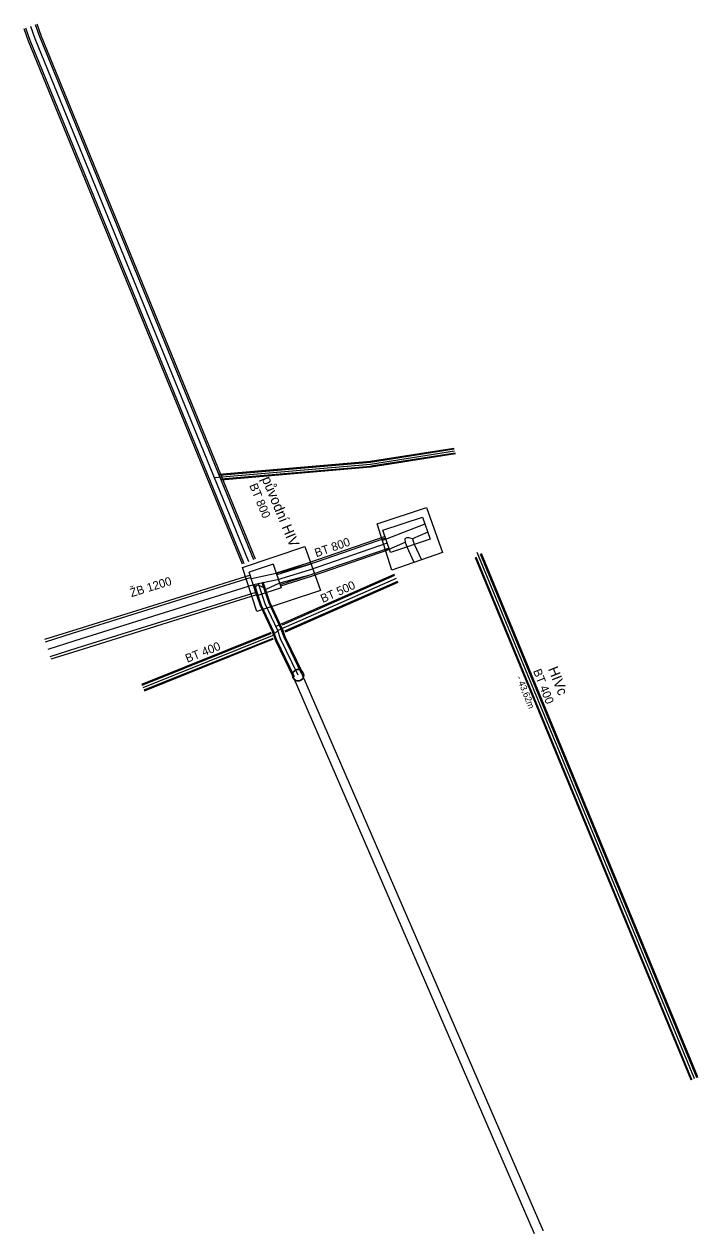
# Model space of a CAD drawing. Extents: x -969087 to -122837, y -1605141 to -636627.
# Drawn here: x -545312.4 to -545245.3, y -1121581.6 to -1121461.1 of the extents above; entities that cross this region are included whole.
import ezdxf

# ---------------------------------------------------------------- set-up
doc = ezdxf.new("R2010")
doc.units = 0
for name, color, linetype in [('Vrstva 14', 7, 'Continuous'), ('Vrstva 2', 7, 'Continuous'), ('Vrstva 5', 7, 'Continuous')]:
    doc.layers.add(name, color=color, linetype=linetype)

# ---------------------------------------------------------------- blocks, each defined once
blk = doc.blocks.new('_U116')
at = {"layer": 'Vrstva 5'}
blk.add_lwpolyline([(-0.0168, -0.0081), (-0.0159, -0.0098), (-0.0147, -0.0113), (-0.0135, -0.0129), (-0.0121, -0.0142), (-0.0105, -0.0154), (-0.0088, -0.0164), (-0.0071, -0.0172), (-0.0052, -0.0179), (-0.0033, -0.0183), (-0.0014, -0.0185), (0.0006, -0.0186), (0.0025, -0.0185), (0.0044, -0.0181), (0.0063, -0.0176), (0.0081, -0.0168), (0.0098, -0.0159), (0.0114, -0.0147), (0.0129, -0.0135), (0.0142, -0.0121), (0.0154, -0.0105), (0.0164, -0.0088), (0.0173, -0.0071), (0.0179, -0.0052), (0.0184, -0.0033), (0.0186, -0.0014), (0.0186, 0.0006), (0.0185, 0.0025), (0.0182, 0.0044), (0.0176, 0.0063), (0.0168, 0.0081), (0.0159, 0.0098), (0.0148, 0.0114), (0.0135, 0.0129), (0.0121, 0.0142), (0.0106, 0.0154), (0.0089, 0.0165), (0.0071, 0.0173), (0.0052, 0.0179), (0.0034, 0.0183), (0.0014, 0.0186), (-0.0005, 0.0187), (-0.0025, 0.0185), (-0.0044, 0.0182), (-0.0063, 0.0176), (-0.0081, 0.0168), (-0.0098, 0.0159), (-0.0114, 0.0148), (-0.0128, 0.0136), (-0.0142, 0.0121), (-0.0154, 0.0105), (-0.0164, 0.0089), (-0.0173, 0.0071), (-0.0179, 0.0053), (-0.0183, 0.0034), (-0.0186, 0.0014), (-0.0186, -0.0006), (-0.0185, -0.0024), (-0.0181, -0.0044), (-0.0175, -0.0063), (-0.0168, -0.0081)], dxfattribs=at)

msp = doc.modelspace()

# ---------------------------------------------------------------- linework, layer by layer
at = {"layer": 'Vrstva 14'}
for points in [[(-545276.69, -1121511.52), (-545272.75, -1121510.2), (-545272, -1121512.41), (-545275.94, -1121513.74), (-545276.69, -1121511.52)], [(-545272.51, -1121510.91), (-545276.39, -1121512.41), (-545276.74, -1121512.54)], [(-545272.24, -1121511.71), (-545273.76, -1121512.38), (-545273.57, -1121512.94)], [(-545276.44, -1121513.5), (-545276.06, -1121513.4), (-545274.47, -1121512.7), (-545274.29, -1121513.23)], [(-545273.76, -1121512.37), (-545273.99, -1121512.3), (-545274.13, -1121512.28), (-545274.33, -1121512.28), (-545274.47, -1121512.33), (-545274.53, -1121512.44), (-545274.48, -1121512.69)], [(-545273.58, -1121512.9), (-545272.86, -1121514.45)], [(-545273.6, -1121514.74), (-545274.29, -1121513.22)], [(-545287.63, -1121514.89), (-545290.02, -1121515.69)], [(-545287.63, -1121514.89), (-545286.84, -1121517.26), (-545289.24, -1121518.05), (-545290.02, -1121515.69)], [(-545283.87, -1121514.87), (-545284.27, -1121515.01), (-545287.32, -1121515.82)], [(-545287.32, -1121515.82), (-545289.8, -1121516.35)], [(-545283.51, -1121515.84), (-545283.97, -1121516), (-545287, -1121516.8), (-545288.36, -1121517.41), (-545288.51, -1121517.28), (-545288.75, -1121517.14), (-545289.03, -1121517.02), (-545289.23, -1121516.99), (-545289.34, -1121517.13), (-545289.43, -1121517.23), (-545289.4, -1121517.42), (-545289.37, -1121517.64), (-545289.33, -1121517.82), (-545289.33, -1121517.81), (-545288.84, -1121519.2), (-545288.73, -1121519.42)]]:
    msp.add_lwpolyline(points, dxfattribs=at)
at = {"layer": 'Vrstva 2'}
for p, q in [((-545269.63, -1121503.36), (-545277.96, -1121504.68)), ((-545269.61, -1121503.45), (-545277.95, -1121504.77)), ((-545277.94, -1121504.68), (-545293.03, -1121505.97)), ((-545269.58, -1121503.65), (-545277.92, -1121504.96)), ((-545269.51, -1121503.83), (-545277.89, -1121505.15)), ((-545269.46, -1121503.92), (-545277.87, -1121505.24)), ((-545277.92, -1121504.96), (-545293.46, -1121506.29)), ((-545277.94, -1121504.77), (-545292.99, -1121506.06)), ((-545277.9, -1121505.16), (-545292.84, -1121506.43)), ((-545277.89, -1121505.25), (-545292.8, -1121506.52))]:
    msp.add_line(p, q, dxfattribs=at)
for points in [[(-545289.56, -1121514.45), (-545310.86, -1121462.38), (-545311.29, -1121461.17)], [(-545289.4, -1121514.39), (-545310.71, -1121462.32), (-545311.13, -1121461.11)], [(-545290.68, -1121514.91), (-545311.99, -1121462.81), (-545312.43, -1121461.56)], [(-545290.52, -1121514.85), (-545311.84, -1121462.75), (-545312.27, -1121461.51)], [(-545290.04, -1121514.65), (-545311.35, -1121462.56), (-545311.78, -1121461.34)], [(-545277.27, -1121510.89), (-545272.37, -1121509.24), (-545270.77, -1121513.75), (-545275.81, -1121515.49), (-545277.27, -1121510.89)], [(-545276.26, -1121512.8), (-545284.04, -1121515.48), (-545287.19, -1121516.47), (-545289.59, -1121516.96)], [(-545276.48, -1121512.15), (-545284.26, -1121514.82), (-545287.33, -1121515.79)], [(-545276.43, -1121512.31), (-545284.21, -1121514.98), (-545287.28, -1121515.95)], [(-545290.67, -1121515.23), (-545284.48, -1121513.14), (-545282.92, -1121517.52), (-545289.27, -1121519.6), (-545290.67, -1121515.23)], [(-545276.09, -1121513.29), (-545283.88, -1121515.97), (-545286.95, -1121516.94)], [(-545276.04, -1121513.45), (-545283.83, -1121516.13), (-545286.9, -1121517.1)], [(-545245.99, -1121566.29), (-545246.04, -1121566.19), (-545267.49, -1121514.26)], [(-545245.9, -1121566.26), (-545245.95, -1121566.15), (-545267.41, -1121514.2)], [(-545245.66, -1121566.16), (-545245.71, -1121566.05), (-545267.31, -1121513.75)], [(-545245.42, -1121566.06), (-545245.47, -1121565.95), (-545266.97, -1121513.91)], [(-545245.33, -1121566.02), (-545245.38, -1121565.91), (-545266.89, -1121513.85)], [(-545289.9, -1121515.98), (-545307.71, -1121521.56), (-545310.4, -1121522.41)], [(-545289.83, -1121516.22), (-545307.64, -1121521.8), (-545310.33, -1121522.65)], [(-545286.72, -1121521.31), (-545287.95, -1121518.67), (-545288.62, -1121516.7)], [(-545275.57, -1121515.91), (-545287.36, -1121521.12)], [(-545275.39, -1121516.31), (-545287.18, -1121521.52)], [(-545275.53, -1121516.02), (-545286.73, -1121520.97)], [(-545275.26, -1121516.61), (-545286.49, -1121521.57)], [(-545275.22, -1121516.71), (-545286.45, -1121521.67)], [(-545289.59, -1121516.96), (-545307.4, -1121522.54), (-545310.09, -1121523.39)], [(-545289.59, -1121516.96), (-545307.4, -1121522.54), (-545310.09, -1121523.39)], [(-545289.36, -1121517.71), (-545307.17, -1121523.28), (-545309.86, -1121524.13)], [(-545287.64, -1121521.74), (-545288.9, -1121519.05), (-545289.59, -1121517.03)], [(-545287.54, -1121521.69), (-545288.79, -1121519.01), (-545289.47, -1121516.99)], [(-545287.18, -1121521.52), (-545288.42, -1121518.86), (-545289.1, -1121516.86)], [(-545286.83, -1121521.36), (-545288.06, -1121518.72), (-545288.74, -1121516.74)], [(-545289.29, -1121517.94), (-545307.09, -1121523.52), (-545309.78, -1121524.37)], [(-545300.57, -1121527.19), (-545287.71, -1121522.01), (-545287.18, -1121521.52)], [(-545285.15, -1121525.96), (-545286.89, -1121522.32), (-545287.18, -1121521.52)], [(-545284.8, -1121525.79), (-545286.53, -1121522.17), (-545286.82, -1121521.39)], [(-545284.69, -1121525.74), (-545286.42, -1121522.12), (-545286.7, -1121521.35)], [(-545300.71, -1121526.86), (-545287.91, -1121521.71), (-545287.85, -1121521.66)], [(-545300.67, -1121526.95), (-545287.85, -1121521.79), (-545287.81, -1121521.76)], [(-545300.48, -1121527.43), (-545287.62, -1121522.26)], [(-545300.44, -1121527.52), (-545287.58, -1121522.35)], [(-545285.61, -1121526.18), (-545287.36, -1121522.52), (-545287.66, -1121521.7)], [(-545285.5, -1121526.12), (-545287.25, -1121522.47), (-545287.55, -1121521.66)], [(-545261.59, -1121581.6), (-545285.61, -1121526.16)], [(-545260.74, -1121581.29), (-545260.75, -1121581.27), (-545284.79, -1121525.8)]]:
    msp.add_lwpolyline(points, dxfattribs=at)
msp.add_circle((-545285.15, -1121525.96), 0.569, dxfattribs=at)

# ---------------------------------------------------------------- block references
at = {"layer": 'Vrstva 2', "xscale": 30.502937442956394, "yscale": 30.502937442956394}
msp.add_blockref('_U116', (-545285.15, -1121525.96), dxfattribs=at)

# ---------------------------------------------------------------- texts
at = {"layer": 'Vrstva 2'}
for s, height, rotation, p in [('BT 800', 0.845, 292.5015, (-545290.03, -1121507.05)), ('původní HIV ', 1.014, 292.5015, (-545288.79, -1121506.38)), ('BT 800', 0.845, 19.1189, (-545283.33, -1121514.21)), ('ŽB 1200 ', 0.845, 17.0591, (-545301.75, -1121518.19)), ('BT 500', 0.845, 24.0148, (-545282.69, -1121518.77)), ('BT 400', 0.845, 21.4976, (-545296.18, -1121524.72)), ('HIVc', 1.014, 291.6312, (-545260.27, -1121525.33)), (' - 43,62m  ', 0.65, 291.6312, (-545263.51, -1121525.95)), ('BT 400', 0.845, 291.6312, (-545261.76, -1121525.53))]:
    msp.add_text(s, height=height, rotation=rotation, dxfattribs=at).set_placement(p)

doc.saveas('drawing.dxf')
